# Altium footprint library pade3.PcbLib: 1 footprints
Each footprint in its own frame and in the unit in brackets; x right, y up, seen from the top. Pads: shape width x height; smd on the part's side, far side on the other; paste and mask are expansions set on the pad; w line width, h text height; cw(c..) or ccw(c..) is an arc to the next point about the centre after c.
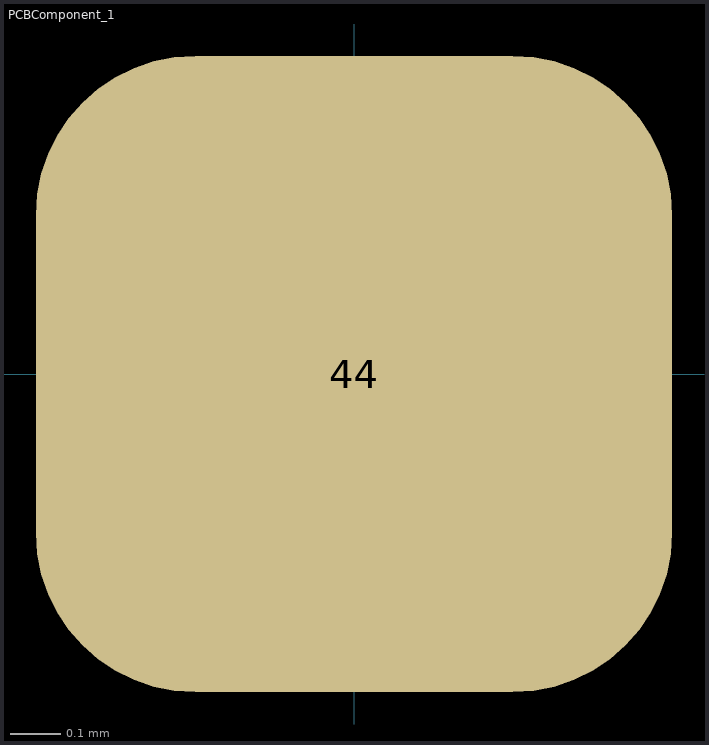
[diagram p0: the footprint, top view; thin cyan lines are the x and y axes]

## PCBComponent_1 [mil]
pads (1):
  rrect50% 50x50 / inner rrect50% 0x0 / far side rrect50% 0x0 all layers, no hole paste-99999 mask+3: 44(0,0)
